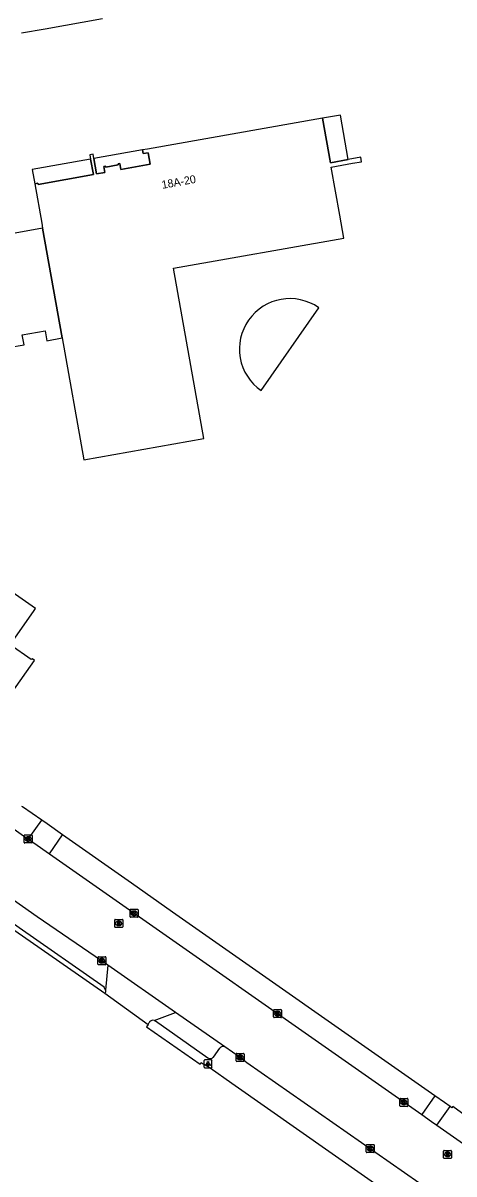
# Model space of a CAD drawing. Extents: x 155018 to 156648, y 383980 to 385733.
# Drawn here: x 155265.9 to 155319.7, y 385106.9 to 385250.7 of the extents above; entities that cross this region are included whole.
import ezdxf

# ---------------------------------------------------------------- set-up
doc = ezdxf.new("R2010")
doc.units = 0
for name, color, linetype in [('IMGEO_Hek', 7, 'Continuous'), ('IMGEO_Kolk', 7, 'Continuous'), ('IMGEO_Lichtpunt', 7, 'Continuous'), ('IMGEO_Pand', 7, 'Continuous'), ('IMGEO_Pand_nummerreeks', 7, 'Continuous'), ('IMGEO_Pand_overbouw', 7, 'Continuous'), ('IMGEO_Parkeervlak_open', 7, 'Continuous'), ('IMGEO_Rijbaan_lokaal_gesloten', 7, 'Continuous'), ('IMGEO_Rijbaan_lokaal_open', 7, 'Continuous'), ('IMGEO_Rioolput', 7, 'Continuous'), ('IMGEO_Voetpad_open', 7, 'Continuous')]:
    doc.layers.add(name, color=color, linetype=linetype)

msp = doc.modelspace()

# ---------------------------------------------------------------- linework, layer by layer
at = {"layer": 'IMGEO_Hek'}
for points in [[(155288.02, 385120.66), (155288.14, 385120.83)], [(155288.53, 385120.61), (155288.14, 385120.83)], [(155289.29, 385120.2), (155288.53, 385120.61)]]:
    msp.add_lwpolyline(points, dxfattribs=at)
at = {"layer": 'IMGEO_Kolk'}
for p, q in [((155266.05, 385148.37), (155266.05, 385149.23)), ((155266.12, 385149.3), (155266.98, 385149.3)), ((155266.56, 385148.52), (155266.53, 385148.52)), ((155266.54, 385149.08), (155266.56, 385149.08)), ((155267.05, 385149.23), (155267.05, 385148.37)), ((155266.98, 385148.3), (155266.12, 385148.3)), ((155279.28, 385139.09), (155279.28, 385139.95)), ((155279.35, 385140.02), (155280.2, 385140.02)), ((155279.77, 385139.8), (155279.79, 385139.8)), ((155280.28, 385139.95), (155280.28, 385139.09)), ((155280.2, 385139.02), (155279.35, 385139.02)), ((155279.79, 385139.24), (155279.76, 385139.24)), ((155275.26, 385133.15), (155275.26, 385134)), ((155275.34, 385134.08), (155276.19, 385134.08)), ((155276.26, 385134), (155276.26, 385133.15)), ((155276.19, 385133.08), (155275.34, 385133.08)), ((155275.75, 385133.86), (155275.77, 385133.86)), ((155275.77, 385133.3), (155275.75, 385133.3)), ((155297.19, 385126.56), (155297.19, 385127.41)), ((155297.27, 385127.49), (155298.12, 385127.49)), ((155297.68, 385127.27), (155297.7, 385127.27)), ((155298.19, 385127.41), (155298.19, 385126.56)), ((155298.12, 385126.49), (155297.27, 385126.49)), ((155297.7, 385126.71), (155297.68, 385126.71)), ((155292.53, 385121.08), (155292.53, 385121.93)), ((155292.6, 385122), (155293.45, 385122)), ((155293.45, 385121), (155292.6, 385121)), ((155293.04, 385121.22), (155293.01, 385121.22)), ((155293.02, 385121.78), (155293.04, 385121.78)), ((155293.53, 385121.93), (155293.53, 385121.08)), ((155312.96, 385115.46), (155312.96, 385116.31)), ((155313.04, 385116.39), (155313.89, 385116.39)), ((155313.89, 385115.39), (155313.04, 385115.39)), ((155313.45, 385116.17), (155313.48, 385116.17)), ((155313.47, 385115.61), (155313.45, 385115.61)), ((155313.96, 385116.31), (155313.96, 385115.46)), ((155308.78, 385109.69), (155308.78, 385110.54)), ((155308.85, 385110.62), (155309.7, 385110.62)), ((155309.7, 385109.62), (155308.85, 385109.62)), ((155309.26, 385110.4), (155309.29, 385110.4)), ((155309.29, 385109.84), (155309.26, 385109.84)), ((155309.78, 385110.54), (155309.78, 385109.69))]:
    msp.add_line(p, q, dxfattribs=at)
for points in [[(155266.05, 385148.37), (155266.05, 385149.23)], [(155266.12, 385149.3), (155266.98, 385149.3)], [(155266.37, 385149), (155266.49, 385149), (155266.49, 385148.85), (155266.62, 385149), (155266.79, 385149), (155266.64, 385148.85), (155266.79, 385148.6), (155266.64, 385148.6), (155266.56, 385148.76), (155266.49, 385148.7), (155266.49, 385148.6), (155266.37, 385148.6), (155266.37, 385149)], [(155267.05, 385149.23), (155267.05, 385148.37)], [(155266.98, 385148.3), (155266.12, 385148.3)], [(155279.28, 385139.09), (155279.28, 385139.95)], [(155279.35, 385140.02), (155280.2, 385140.02)], [(155279.6, 385139.72), (155279.72, 385139.72), (155279.72, 385139.57), (155279.85, 385139.72), (155280.02, 385139.72), (155279.87, 385139.57), (155280.02, 385139.32), (155279.87, 385139.32), (155279.79, 385139.48), (155279.72, 385139.42), (155279.72, 385139.32), (155279.6, 385139.32), (155279.6, 385139.72)], [(155280.28, 385139.95), (155280.28, 385139.09)], [(155280.2, 385139.02), (155279.35, 385139.02)], [(155275.26, 385133.15), (155275.26, 385134)], [(155275.34, 385134.08), (155276.19, 385134.08)], [(155276.26, 385134), (155276.26, 385133.15)], [(155276.19, 385133.08), (155275.34, 385133.08)], [(155275.58, 385133.78), (155275.71, 385133.78), (155275.71, 385133.63), (155275.83, 385133.78), (155276, 385133.78), (155275.85, 385133.63), (155276.01, 385133.38), (155275.85, 385133.38), (155275.77, 385133.54), (155275.71, 385133.48), (155275.71, 385133.38), (155275.58, 385133.38), (155275.58, 385133.78)], [(155297.19, 385126.56), (155297.19, 385127.41)], [(155297.27, 385127.49), (155298.12, 385127.49)], [(155297.51, 385127.19), (155297.64, 385127.19), (155297.64, 385127.03), (155297.76, 385127.19), (155297.93, 385127.19), (155297.78, 385127.04), (155297.94, 385126.79), (155297.78, 385126.79), (155297.7, 385126.95), (155297.64, 385126.88), (155297.64, 385126.79), (155297.51, 385126.79), (155297.51, 385127.19)], [(155298.19, 385127.41), (155298.19, 385126.56)], [(155298.12, 385126.49), (155297.27, 385126.49)], [(155292.53, 385121.08), (155292.53, 385121.93)], [(155292.6, 385122), (155293.45, 385122)], [(155293.45, 385121), (155292.6, 385121)], [(155292.85, 385121.7), (155292.97, 385121.7), (155292.97, 385121.55), (155293.1, 385121.7), (155293.27, 385121.7), (155293.12, 385121.55), (155293.27, 385121.3), (155293.12, 385121.3), (155293.04, 385121.47), (155292.97, 385121.4), (155292.97, 385121.3), (155292.85, 385121.3), (155292.85, 385121.7)], [(155293.53, 385121.93), (155293.53, 385121.08)], [(155312.96, 385115.46), (155312.96, 385116.31)], [(155313.04, 385116.39), (155313.89, 385116.39)], [(155313.89, 385115.39), (155313.04, 385115.39)], [(155313.28, 385116.09), (155313.41, 385116.09), (155313.41, 385115.94), (155313.54, 385116.09), (155313.7, 385116.09), (155313.56, 385115.94), (155313.71, 385115.69), (155313.56, 385115.69), (155313.47, 385115.85), (155313.41, 385115.78), (155313.41, 385115.69), (155313.28, 385115.69), (155313.28, 385116.09)], [(155313.96, 385116.31), (155313.96, 385115.46)], [(155308.78, 385109.69), (155308.78, 385110.54)], [(155308.85, 385110.62), (155309.7, 385110.62)], [(155309.7, 385109.62), (155308.85, 385109.62)], [(155309.1, 385110.32), (155309.22, 385110.32), (155309.22, 385110.17), (155309.35, 385110.32), (155309.51, 385110.32), (155309.37, 385110.17), (155309.52, 385109.92), (155309.37, 385109.92), (155309.28, 385110.08), (155309.22, 385110.02), (155309.22, 385109.92), (155309.1, 385109.92), (155309.1, 385110.32)], [(155309.78, 385110.54), (155309.78, 385109.69)]]:
    msp.add_lwpolyline(points, dxfattribs=at)
for centre, start, end in [((155266.13, 385149.22), 91.552, 178.448), ((155266.13, 385149.22), 91.552, 178.448), ((155266.13, 385148.37), 181.552, 268.448), ((155266.13, 385148.37), 181.552, 268.448), ((155266.97, 385149.22), 1.552, 88.448), ((155266.97, 385149.22), 1.552, 88.448), ((155266.97, 385148.37), 271.552, 358.448), ((155266.97, 385148.37), 271.552, 358.448), ((155279.35, 385139.94), 91.552, 178.448), ((155279.35, 385139.94), 91.552, 178.448), ((155280.2, 385139.94), 1.552, 88.448), ((155280.2, 385139.94), 1.552, 88.448), ((155279.35, 385139.09), 181.552, 268.448), ((155279.35, 385139.09), 181.552, 268.448), ((155280.2, 385139.09), 271.552, 358.448), ((155280.2, 385139.09), 271.552, 358.448), ((155275.34, 385134), 91.552, 178.448), ((155275.34, 385134), 91.552, 178.448), ((155276.19, 385134), 1.552, 88.448), ((155276.19, 385134), 1.552, 88.448), ((155275.34, 385133.15), 181.552, 268.448), ((155275.34, 385133.15), 181.552, 268.448), ((155276.19, 385133.15), 271.552, 358.448), ((155276.19, 385133.15), 271.552, 358.448), ((155297.27, 385127.41), 91.552, 178.448), ((155297.27, 385127.41), 91.552, 178.448), ((155298.12, 385127.41), 1.552, 88.448), ((155298.12, 385127.41), 1.552, 88.448), ((155297.27, 385126.56), 181.552, 268.448), ((155297.27, 385126.56), 181.552, 268.448), ((155298.12, 385126.56), 271.552, 358.448), ((155298.12, 385126.56), 271.552, 358.448), ((155292.6, 385121.93), 91.552, 178.448), ((155292.6, 385121.93), 91.552, 178.448), ((155292.6, 385121.08), 181.552, 268.448), ((155292.6, 385121.08), 181.552, 268.448), ((155293.45, 385121.93), 1.552, 88.448), ((155293.45, 385121.93), 1.552, 88.448), ((155293.45, 385121.08), 271.552, 358.448), ((155293.45, 385121.08), 271.552, 358.448), ((155313.04, 385116.31), 91.552, 178.448), ((155313.04, 385116.31), 91.552, 178.448), ((155313.04, 385115.46), 181.552, 268.448), ((155313.04, 385115.46), 181.552, 268.448), ((155313.89, 385116.31), 1.552, 88.448), ((155313.89, 385116.31), 1.552, 88.448), ((155313.89, 385115.46), 271.552, 358.448), ((155313.89, 385115.46), 271.552, 358.448), ((155308.85, 385110.54), 91.552, 178.448), ((155308.85, 385110.54), 91.552, 178.448), ((155308.85, 385109.69), 181.552, 268.448), ((155308.85, 385109.69), 181.552, 268.448), ((155309.7, 385110.54), 1.552, 88.448), ((155309.7, 385110.54), 1.552, 88.448), ((155309.7, 385109.69), 271.552, 358.448), ((155309.7, 385109.69), 271.552, 358.448)]:
    msp.add_arc(centre, 0.0765, start, end, dxfattribs=at)
for centre, major_axis, ratio, start_param, end_param in [((155266.54, 385148.8), (-0.387, 0.002), 0.722429, 4.712389, 7.853982), ((155266.56, 385148.8), (-0.39, 0.002), 0.717154, 1.570796, 4.712389), ((155279.76, 385139.52), (-0.387, 0.002), 0.722429, 4.712389, 7.853982), ((155279.79, 385139.52), (-0.39, 0.002), 0.717154, 1.570796, 4.712389), ((155275.75, 385133.58), (-0.387, 0.002), 0.722429, 4.712389, 7.853982), ((155275.77, 385133.58), (-0.39, 0.002), 0.717154, 1.570796, 4.712389), ((155297.68, 385126.99), (-0.387, 0.002), 0.722429, 4.712389, 7.853982), ((155297.7, 385126.99), (-0.39, 0.002), 0.717154, 1.570796, 4.712389), ((155293.01, 385121.5), (-0.387, 0.002), 0.722429, 4.712389, 7.853982), ((155293.04, 385121.5), (-0.39, 0.002), 0.717154, 1.570796, 4.712389), ((155313.45, 385115.89), (-0.387, 0.002), 0.722429, 4.712389, 7.853982), ((155313.47, 385115.89), (-0.39, 0.002), 0.717154, 1.570796, 4.712389), ((155309.26, 385110.12), (-0.387, 0.002), 0.722429, 4.712389, 7.853982), ((155309.29, 385110.12), (-0.39, 0.002), 0.717154, 1.570796, 4.712389)]:
    msp.add_ellipse(centre, major_axis=major_axis, ratio=ratio, start_param=start_param, end_param=end_param, dxfattribs=at)
at = {"layer": 'IMGEO_Lichtpunt'}
for p, q in [((155288.51, 385121.11), (155288.51, 385120.3)), ((155288.51, 385121.11), (155288.51, 385120.3)), ((155289.42, 385121.2), (155288.61, 385121.2)), ((155289.42, 385121.2), (155288.61, 385121.2)), ((155289.51, 385120.3), (155289.51, 385121.11)), ((155289.51, 385120.3), (155289.51, 385121.11)), ((155288.61, 385120.21), (155289.42, 385120.21)), ((155288.61, 385120.21), (155289.42, 385120.21))]:
    msp.add_line(p, q, dxfattribs=at)
for points in [[(155288.89, 385120.77), (155288.93, 385120.74), (155288.74, 385120.48), (155288.7, 385120.51), (155288.89, 385120.77)], [(155288.99, 385120.72), (155289.04, 385120.72), (155289.04, 385120.4), (155288.99, 385120.4), (155288.99, 385120.72)], [(155289.1, 385120.74), (155289.14, 385120.77), (155289.33, 385120.51), (155289.29, 385120.48), (155289.1, 385120.74)]]:
    msp.add_lwpolyline(points, dxfattribs=at)
msp.add_circle((155289.01, 385120.91), 0.0994, dxfattribs=at)
for centre, start, end in [((155288.61, 385121.11), 90, 180), ((155288.61, 385121.11), 90, 180), ((155289.42, 385121.11), 0, 90), ((155289.42, 385121.11), 0, 90), ((155288.61, 385120.3), 180, 270), ((155288.61, 385120.3), 180, 270), ((155289.42, 385120.3), 270, 0), ((155289.42, 385120.3), 270, 360)]:
    msp.add_arc(centre, 0.0946, start, end, dxfattribs=at)
at = {"layer": 'IMGEO_Pand'}
for points in [[(155305.48, 385226.73), (155304.4, 385232.74), (155307.07, 385233.22), (155308.19, 385233.42), (155308.09, 385233.97), (155306.53, 385233.69), (155304.3, 385233.29), (155303.31, 385238.87), (155281.45, 385235), (155280.82, 385234.89), (155280.9, 385234.44), (155281.53, 385234.55), (155281.79, 385233.11), (155278.13, 385232.45), (155278, 385233.18), (155277.78, 385233.14), (155277.8, 385233.03), (155276.25, 385232.75), (155276.23, 385232.86), (155276, 385232.82), (155276.13, 385232.09), (155275.1, 385231.91), (155274.76, 385233.82), (155274.67, 385234.35), (155274.26, 385234.28), (155274.36, 385233.75), (155274.7, 385231.82), (155267.8, 385230.58), (155267.77, 385230.72), (155267.38, 385230.65), (155268.25, 385225.73), (155268.35, 385225.11), (155270.79, 385211.41), (155273.51, 385196.17), (155288.48, 385198.84), (155284.72, 385220.1), (155305.98, 385223.88), (155305.48, 385226.73)], [(155295.64, 385204.84), (155302.84, 385215.17)], [(155264.56, 385167.16), (155267.34, 385171.12), (155267.08, 385171.3), (155266.92, 385171.22), (155264.31, 385173.05), (155267.3, 385177.34), (155267.48, 385177.6), (155252.71, 385187.91)]]:
    msp.add_lwpolyline(points, dxfattribs=at)
for centre, radius, start, end in [((155299.24, 385210), 6.31, 55.1578, 144.8448), ((155299.19, 385210), 6.26, 144.6334, 235.5343)]:
    msp.add_arc(centre, radius, start, end, dxfattribs=at)
at = {"layer": 'IMGEO_Pand_overbouw'}
for points in [[(155306.53, 385233.69), (155305.54, 385239.25), (155303.31, 385238.87), (155304.3, 385233.29)], [(155280.82, 385234.89), (155274.76, 385233.82), (155275.1, 385231.91), (155276.13, 385232.09), (155276, 385232.82), (155276.23, 385232.86), (155276.25, 385232.75), (155277.8, 385233.03), (155277.78, 385233.14), (155278, 385233.18), (155278.13, 385232.45), (155281.79, 385233.11), (155281.53, 385234.55), (155280.9, 385234.44)], [(155267.38, 385230.65), (155267.77, 385230.72), (155267.8, 385230.58), (155274.7, 385231.82), (155274.36, 385233.75), (155267.07, 385232.46)], [(155264.1, 385210.2), (155266.04, 385210.53), (155265.82, 385211.79), (155268.66, 385212.3), (155268.88, 385211.04), (155270.79, 385211.41), (155268.35, 385225.11), (155261.67, 385223.9), (155262.05, 385221.66), (155263.88, 385211.44)]]:
    msp.add_lwpolyline(points, close=True, dxfattribs=at)
at = {"layer": 'IMGEO_Parkeervlak_open'}
msp.add_lwpolyline([(155317.35, 385116.7), (155284.56, 385139.65), (155279.45, 385143.26), (155270.84, 385149.33)], dxfattribs=at)
at = {"layer": 'IMGEO_Rijbaan_lokaal_gesloten'}
for points in [[(155264.15, 385150.48), (155264.22, 385150.43), (155266.57, 385148.78)], [(155266.57, 385148.78), (155267.26, 385148.3), (155269.21, 385146.94)], [(155269.21, 385146.94), (155315.7, 385114.36)], [(155276.49, 385133.02), (155267.69, 385139.07), (155262.14, 385142.93)], [(155284.97, 385127.1), (155276.49, 385133.02)], [(155291.11, 385122.81), (155284.97, 385127.1)], [(155318.91, 385103.34), (155293.87, 385120.84), (155293.03, 385121.5), (155291.11, 385122.81)], [(155315.7, 385114.36), (155316.9, 385113.52), (155317.59, 385113.03)], [(155317.59, 385113.03), (155324.53, 385108.17)]]:
    msp.add_lwpolyline(points, dxfattribs=at)
at = {"layer": 'IMGEO_Rijbaan_lokaal_open'}
for points in [[(155268.25, 385151.15), (155265.84, 385152.81), (155265.78, 385152.85)], [(155266.57, 385148.78), (155268.25, 385151.15)], [(155276.49, 385133.02), (155276.23, 385129.93)], [(155276.13, 385129.55), (155281.52, 385125.64)], [(155282.31, 385126.12), (155284.97, 385127.1)], [(155281.52, 385125.64), (155281.66, 385125.85), (155281.73, 385125.94)], [(155317.59, 385113.03), (155319.24, 385115.37)], [(155326.19, 385110.55), (155319.58, 385115.36), (155319.46, 385115.21), (155319.24, 385115.37)]]:
    msp.add_lwpolyline(points, dxfattribs=at)
for centre, radius, start, end in [((155275.87, 385129.81), 0.376, 314.7173, 18.0543), ((155282.13, 385125.65), 0.5, 69.6477, 144.5993)]:
    msp.add_arc(centre, radius, start, end, dxfattribs=at)
at = {"layer": 'IMGEO_Rioolput'}
for p, q in [((155277.36, 385137.83), (155277.36, 385138.68)), ((155277.44, 385138.75), (155278.29, 385138.75)), ((155277.85, 385138.53), (155277.88, 385138.53)), ((155278.36, 385138.68), (155278.36, 385137.83)), ((155278.29, 385137.75), (155277.44, 385137.75)), ((155277.87, 385137.97), (155277.85, 385137.97)), ((155318.42, 385108.96), (155318.42, 385109.81)), ((155318.49, 385109.89), (155319.35, 385109.89)), ((155318.91, 385109.67), (155318.93, 385109.67)), ((155319.42, 385109.81), (155319.42, 385108.96)), ((155319.35, 385108.89), (155318.49, 385108.89)), ((155318.93, 385109.11), (155318.9, 385109.11))]:
    msp.add_line(p, q, dxfattribs=at)
for points in [[(155277.36, 385137.83), (155277.36, 385138.68)], [(155277.44, 385138.75), (155278.29, 385138.75)], [(155277.95, 385138.45), (155277.7, 385138.45), (155277.7, 385138.05)], [(155277.88, 385138.37), (155277.82, 385138.37), (155277.82, 385138.29)], [(155277.82, 385138.29), (155277.88, 385138.29)], [(155278.36, 385138.68), (155278.36, 385137.83)], [(155278.29, 385137.75), (155277.44, 385137.75)], [(155277.7, 385138.05), (155277.82, 385138.05), (155277.82, 385138.22), (155277.84, 385138.22)], [(155277.88, 385138.19), (155277.95, 385138.05), (155278.09, 385138.05), (155278.03, 385138.18)], [(155318.42, 385108.96), (155318.42, 385109.81)], [(155318.49, 385109.89), (155319.35, 385109.89)], [(155319.01, 385109.59), (155318.76, 385109.59), (155318.76, 385109.19)], [(155318.93, 385109.51), (155318.88, 385109.51), (155318.88, 385109.43)], [(155319.42, 385109.81), (155319.42, 385108.96)], [(155319.35, 385108.89), (155318.49, 385108.89)], [(155318.76, 385109.19), (155318.88, 385109.19), (155318.88, 385109.35), (155318.89, 385109.35)], [(155318.88, 385109.43), (155318.93, 385109.43)], [(155318.94, 385109.32), (155319.01, 385109.19), (155319.15, 385109.19), (155319.08, 385109.31)]]:
    msp.add_lwpolyline(points, dxfattribs=at)
for centre, radius, start, end in [((155277.44, 385138.68), 0.0765, 91.552, 178.448), ((155277.44, 385138.68), 0.0765, 91.552, 178.448), ((155277.88, 385138.28), 0.0964, 77.0061, 93.1865), ((155277.86, 385138.48), 0.19, 274.7715, 282.9687), ((155277.9, 385138.33), 0.0378, 276.6634, 79.6772), ((155277.95, 385138.34), 0.109, 350.3612, 89.416), ((155277.95, 385138.34), 0.112, 277.5842, 350.9817), ((155278.29, 385138.68), 0.0765, 1.552, 88.448), ((155278.29, 385138.68), 0.0765, 1.552, 88.448), ((155277.44, 385137.83), 0.0765, 181.552, 268.448), ((155277.44, 385137.83), 0.0765, 181.552, 268.448), ((155277.83, 385138.16), 0.0533, 26.0293, 88.6989), ((155277.93, 385138.13), 0.108, 29.5134, 73.7905), ((155278.29, 385137.83), 0.0765, 271.552, 358.448), ((155278.29, 385137.83), 0.0765, 271.552, 358.448), ((155318.5, 385109.81), 0.0765, 91.552, 178.448), ((155318.5, 385109.81), 0.0765, 91.552, 178.448), ((155318.94, 385109.41), 0.0964, 77.0061, 93.1865), ((155318.95, 385109.47), 0.0378, 276.6634, 79.6772), ((155319.01, 385109.48), 0.109, 350.3612, 89.416), ((155319.34, 385109.81), 0.0765, 1.552, 88.448), ((155319.34, 385109.81), 0.0765, 1.552, 88.448), ((155318.5, 385108.96), 0.0765, 181.552, 268.448), ((155318.5, 385108.96), 0.0765, 181.552, 268.448), ((155318.89, 385109.3), 0.0533, 26.0293, 88.6989), ((155318.92, 385109.62), 0.19, 274.7715, 282.9687), ((155319.01, 385109.48), 0.112, 277.5842, 350.9817), ((155318.99, 385109.26), 0.108, 29.5134, 73.7905), ((155319.34, 385108.96), 0.0765, 271.552, 358.448), ((155319.34, 385108.96), 0.0765, 271.552, 358.448)]:
    msp.add_arc(centre, radius, start, end, dxfattribs=at)
for centre, major_axis, ratio, start_param, end_param in [((155277.85, 385138.25), (-0.387, 0.002), 0.722429, 4.712389, 7.853982), ((155277.87, 385138.25), (-0.39, 0.002), 0.717154, 1.570796, 4.712389), ((155318.91, 385109.39), (-0.387, 0.002), 0.722429, 4.712389, 7.853982), ((155318.93, 385109.39), (-0.39, 0.002), 0.717154, 1.570796, 4.712389)]:
    msp.add_ellipse(centre, major_axis=major_axis, ratio=ratio, start_param=start_param, end_param=end_param, dxfattribs=at)
at = {"layer": 'IMGEO_Voetpad_open'}
for points in [[(155275.82, 385251.27), (155268.7, 385250), (155265.72, 385249.47)], [(155212.56, 385173.84), (155243.35, 385152.36), (155276.13, 385129.55)], [(155270.84, 385149.33), (155268.92, 385150.68), (155268.25, 385151.15)], [(155269.21, 385146.94), (155270.84, 385149.33)], [(155276.23, 385129.93), (155276.03, 385130.27), (155265.45, 385137.68), (155261.51, 385140.44)], [(155281.52, 385125.64), (155281.33, 385125.34), (155288.02, 385120.66), (155288.14, 385120.83), (155288.53, 385120.61), (155289.29, 385120.2), (155292, 385118.3), (155317.04, 385100.72)], [(155282.31, 385126.12), (155282.45, 385126.07), (155289, 385121.46)], [(155289.69, 385121.55), (155290.47, 385122.65)], [(155317.35, 385116.7), (155315.7, 385114.36)], [(155319.24, 385115.37), (155318.53, 385115.87), (155317.35, 385116.7)]]:
    msp.add_lwpolyline(points, dxfattribs=at)
for centre, radius, start, end in [((155290.88, 385122.39), 0.483, 60.673, 146.9791), ((155289.3, 385121.85), 0.491, 232.3201, 322.8474)]:
    msp.add_arc(centre, radius, start, end, dxfattribs=at)

# ---------------------------------------------------------------- texts
at = {"layer": 'IMGEO_Pand_nummerreeks'}
msp.add_text('18A-20', height=1, rotation=10.1488, dxfattribs=at).set_placement((155283.32, 385230.03))

doc.saveas('drawing.dxf')
